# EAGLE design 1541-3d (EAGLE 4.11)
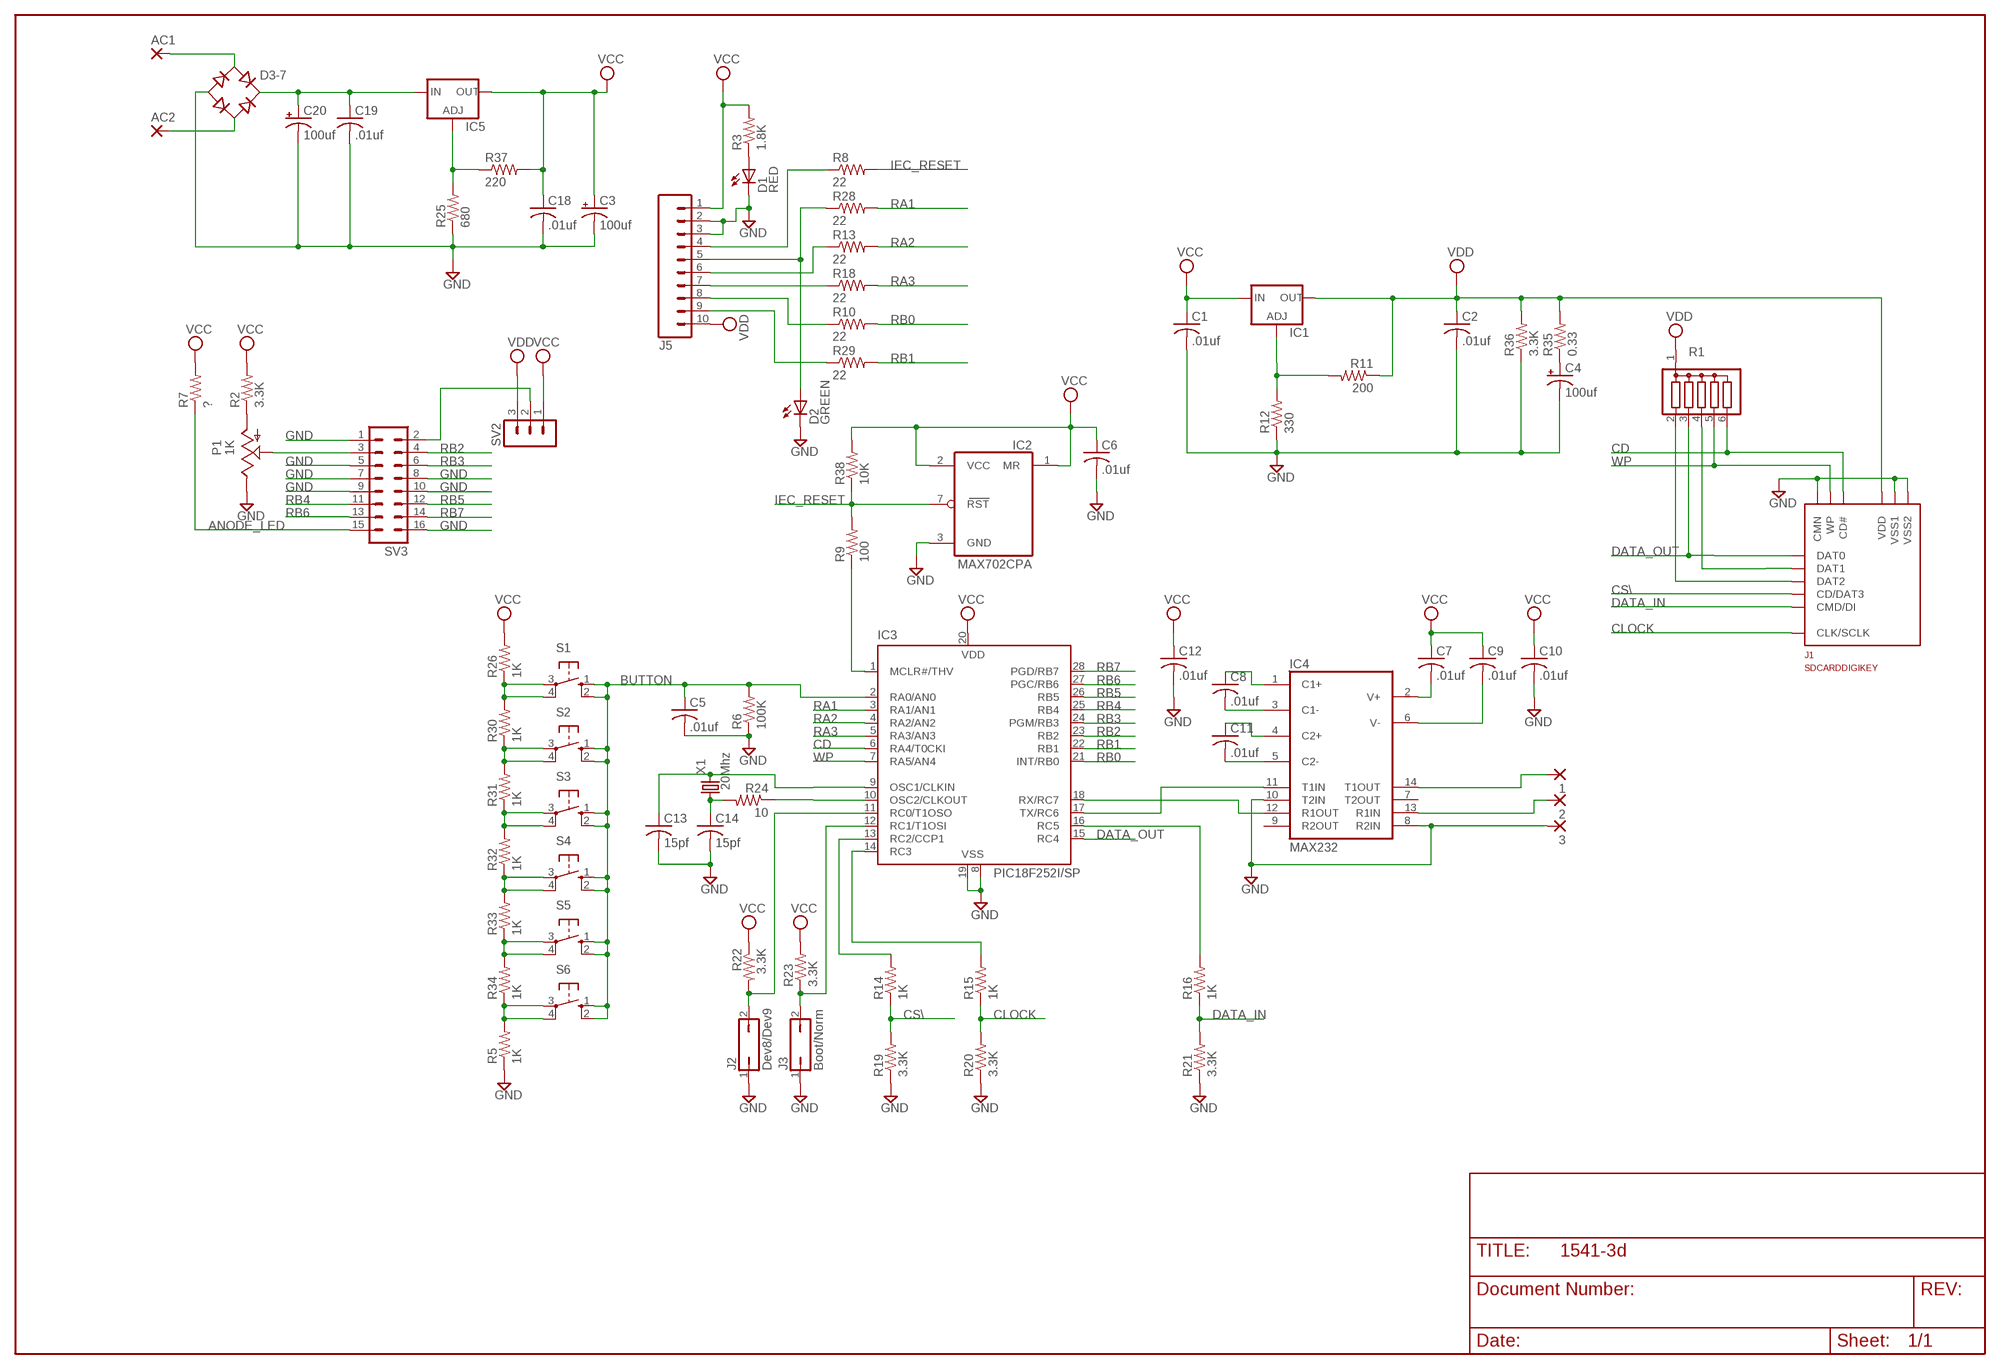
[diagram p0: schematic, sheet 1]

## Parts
1  2,15/1,0  [2,15/1,0]
2  2,15/1,0  [2,15/1,0]
3  2,15/1,0  [2,15/1,0]
AC1  2,15/1,0  [2,15/1,0]
AC2  2,15/1,0  [2,15/1,0]
C1  .01uf  C-US025-024X044  [C025-024X044]
C2  .01uf  C-US025-024X044  [C025-024X044]
C3  100uf  CPOL-USE2-5  [E2-5]
C4  100uf  CPOL-USE2-5  [E2-5]
C5  .01uf  C-US025-024X044  [C025-024X044]
C6  .01uf  C-US025-024X044  [C025-024X044]
C7  .01uf  C-US025-024X044  [C025-024X044]
C8  .01uf  C-US025-024X044  [C025-024X044]
C9  .01uf  C-US025-024X044  [C025-024X044]
C10  .01uf  C-US025-024X044  [C025-024X044]
C11  .01uf  C-US025-024X044  [C025-024X044]
C12  .01uf  C-US025-024X044  [C025-024X044]
C13  15pf  C-US025-024X044  [C025-024X044]
C14  15pf  C-US025-024X044  [C025-024X044]
C18  .01uf  C-US025-024X044  [C025-024X044]
C19  .01uf  C-US025-024X044  [C025-024X044]
C20  100uf  CPOL-USE2-5  [E2-5]
D1  RED  LED3MM  [LED3MM]
D2  GREEN  LED3MM  [LED3MM]
D3-7  RB1A  [RB1A]
IC1  LM317TS  [317TS]
IC2  MAX702CPA  [DIL08]
IC3  PIC18F252I/SP  PIC16F870P  [DIL28-3]
IC4  MAX232  [DIL16]
IC5  LM317TS  [317TS]
J1  SDCARDDIGIKEY  [WM24032]
J2  Dev8/Dev9  JP1Q  [JP1]
J3  Boot/Norm  JP1Q  [JP1]
J5  M10  [10P]
P1  1K  TRIM_US-LI10  [LI10]
R1  G05R  [SIL6]
R2  3.3K  R-US_0207/2V  [0207/2V]
R3  1.8K  R-US_0207/2V  [0207/2V]
R5  1K  R-US_0207/2V  [0207/2V]
R6  100K  R-US_0207/2V  [0207/2V]
R7  ?  R-US_0207/2V  [0207/2V]
R8  22  R-US_0207/2V  [0207/2V]
R9  100  R-US_0207/2V  [0207/2V]
R10  22  R-US_0207/2V  [0207/2V]
R11  200  R-US_0207/2V  [0207/2V]
R12  330  R-US_0207/2V  [0207/2V]
R13  22  R-US_0207/2V  [0207/2V]
R14  1K  R-US_0207/2V  [0207/2V]
R15  1K  R-US_0207/2V  [0207/2V]
R16  1K  R-US_0207/2V  [0207/2V]
R18  22  R-US_0207/2V  [0207/2V]
R19  3.3K  R-US_0207/2V  [0207/2V]
R20  3.3K  R-US_0207/2V  [0207/2V]
R21  3.3K  R-US_0207/2V  [0207/2V]
R22  3.3K  R-US_0207/2V  [0207/2V]
R23  3.3K  R-US_0207/2V  [0207/2V]
R24  10  R-US_0207/2V  [0207/2V]
R25  680  R-US_0207/2V  [0207/2V]
R26  1K  R-US_0207/2V  [0207/2V]
R28  22  R-US_0207/2V  [0207/2V]
R29  22  R-US_0207/2V  [0207/2V]
R30  1K  R-US_0207/2V  [0207/2V]
R31  1K  R-US_0207/2V  [0207/2V]
R32  1K  R-US_0207/2V  [0207/2V]
R33  1K  R-US_0207/2V  [0207/2V]
R34  1K  R-US_0207/2V  [0207/2V]
R35  0.33  R-US_0207/2V  [0207/2V]
R36  3.3K  R-US_0207/2V  [0207/2V]
R37  220  R-US_0207/2V  [0207/2V]
R38  10K  R-US_0207/2V  [0207/2V]
S1  10-XX  [B3F-10XX]
S2  10-XX  [B3F-10XX]
S3  10-XX  [B3F-10XX]
S4  10-XX  [B3F-10XX]
S5  10-XX  [B3F-10XX]
S6  10-XX  [B3F-10XX]
SV2  MA03-1  [MA03-1]
SV3  ML16  [ML16]
X1  20Mhz  CRYTALHC49U70  [HC49U70]

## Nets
ANODE_LED: R7.1 SV3.15
BUTTON: C5.1 IC3.2(RA0/AN0) R6.2 S1.1(S) S1.2(S1) S2.1(S) S2.2(S1) S3.1(S) S3.2(S1) S4.1(S) S4.2(S1) S5.1(S) S5.2(S1) S6.1(S) S6.2(S1)
CD: IC3.6(RA4/T0CKI) J1.CD(CD#) R1.6
CLOCK: J1.5(CLK/SCLK) R15.1 R20.2
CS\: J1.1(CD/DAT3) R14.1 R19.2
DATA_IN: J1.2(CMD/DI) R16.1 R21.2
DATA_OUT: IC3.15(RC4) J1.7(DAT0) R1.3
GND: 3.1(P) C1.2 C2.2 C3.- C4.- C5.2 C6.2 C10.2 C12.2 C13.2 C14.2 C18.2 C19.2 C20.- D1.K(C) D2.K(C) D3-7.- IC2.3(GND) IC3.8(VSS) IC3.19(VSS) IC4.8(R2IN) IC4.10(T2IN) J1.3(VSS1) J1.6(VSS2) J1.CMN J2.1 J3.1 J5.2 J5.3 P1.E R5.1 R6.1 R12.1 R19.1 R20.1 R21.1 R25.1 R36.1 SV3.1 SV3.5 SV3.7 SV3.8 SV3.9 SV3.10 SV3.16
IEC_RESET: IC2.7(RST) R8.2 R9.2 R38.1
N$1: C4.+ R35.1
N$2: J1.9(DAT2) R1.2
N$3: J1.8(DAT1) R1.4
N$4: J5.9 R29.1
N$5: J5.8 R10.1
N$6: J5.7 R18.1
N$7: J5.4 R8.1
N$8: D2.A J5.5 R28.1
N$9: J5.6 R13.1
N$10: D1.A R3.1
N$11: IC3.18(RX/RC7) IC4.12(R1OUT)
N$12: IC3.14(RC3) R15.2
N$13: C14.1 R24.2 X1.1
N$14: IC3.1(MCLR#/THV) R9.1
N$15: C11.1 IC4.4(C2+)
N$16: C11.2 IC4.5(C2-)
N$17: C8.2 IC4.3(C1-)
N$18: C8.1 IC4.1(C1+)
N$19: C7.2 IC4.2(V+)
N$20: C13.1 IC3.9(OSC1/CLKIN) X1.2
N$21: IC3.10(OSC2/CLKOUT) R24.1
N$22: IC3.12(RC1/T1OSI) J3.2 R23.1
N$23: IC3.11(RC0/T1OSO) J2.2 R22.2
N$24: IC3.13(RC2/CCP1) R14.2
N$25: IC3.16(RC5) R16.2
N$26: IC1.1(ADJ) R11.2 R12.2
N$27: IC3.17(TX/RC6) IC4.11(T1IN)
N$28: R26.1 R30.2 S1.3(P) S1.4(P1)
N$29: R30.1 R31.2 S2.3(P) S2.4(P1)
N$30: R31.1 R32.2 S3.3(P) S3.4(P1)
N$31: R5.2 R34.1 S6.3(P) S6.4(P1)
N$32: R33.1 R34.2 S5.3(P) S5.4(P1)
N$33: R32.1 R33.2 S4.3(P) S4.4(P1)
N$34: P1.A R2.1
N$35: SV2.2 SV3.2
N$36: P1.S SV3.3
N$37: C9.2 IC4.6(V-)
N$38: IC5.1(ADJ) R25.2 R37.1
N$39: AC1.1(P) D3-7.AC1
N$40: C19.1 C20.+ D3-7.+ IC5.3(IN)
N$41: AC2.1(P) D3-7.AC2
N$42: 2.1(P) IC4.13(R1IN)
N$43: 1.1(P) IC4.14(T1OUT)
RA1: IC3.3(RA1/AN1) R28.2
RA2: IC3.4(RA2/AN2) R13.2
RA3: IC3.5(RA3/AN3) R18.2
RB0: IC3.21(INT/RB0) R10.2
RB1: IC3.22(RB1) R29.2
RB2: IC3.23(RB2) SV3.4
RB3: IC3.24(PGM/RB3) SV3.6
RB4: IC3.25(RB4) SV3.11
RB5: IC3.26(RB5) SV3.12
RB6: IC3.27(PGC/RB6) SV3.13
RB7: IC3.28(PGD/RB7) SV3.14
VCC: C1.1 C3.+ C6.1 C7.1 C9.1 C10.1 C12.1 C18.1 IC1.3(IN) IC2.1(MR) IC2.2(VCC) IC3.20(VDD) IC5.2(OUT) J5.1 R2.2 R3.2 R7.2 R22.1 R23.2 R26.2 R37.2 R38.2 SV2.1
VDD: C2.1 IC1.2(OUT) J1.4(VDD) J5.10 R1.1 R11.1 R35.2 R36.2 SV2.3
WP: IC3.7(RA5/AN4) J1.WP R1.5
Unconnected: IC4.7(T2OUT) IC4.9(R2OUT)

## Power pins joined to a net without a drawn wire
GND: IC4.15(GND) J1.A1(GND) J1.A2(GND)
VCC: IC4.16(VCC)

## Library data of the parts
1-3 AC1 AC2 = wirepad:2,15/1,0: THROUGH-HOLE PAD
C1 C2 C5-C14 C18 C19 = rcl:C-US: CAPACITOR, American symbol
C3 C4 C20 = rcl:CPOL-US: POLARIZED CAPACITOR, American symbol
D1 D2 = led:LED: LED
D3-7 = rectifier:RB1A: RECTIFIER 1 A
IC1 IC5 = v-reg:LM317TS: VOLTAGE REGULATOR
IC2 = maxim:MAX702CPA: POWER SUPPLY MONITOR
IC3 = microchip:PIC16*870: MICROCONTROLLER flash type
IC4 = maxim:MAX232: RS232 TRANSEIVER
J1 = sdcards:SDCARD: SD Card Holder
J2 J3 = jumper:JP1Q: JUMPER
J5 = con-amp-quick:M10: AMP QUICK CONNECTOR
P1 = pot:TRIM_US-: POTENTIOMETER
R1 = resistor-sil:G05R: SIL RESISTOR
R2 R3 R5-R16 R18-R26 R28-R38 = rcl:R-US_: RESISTOR, American symbol
S1-S6 = switch-omron:10-XX: OMRON SWITCH
SV2 = con-lstb:MA03-1: PIN HEADER
SV3 = con-harting-ml:ML16: HARTING
X1 = crystal:CRYTAL: CRYSTAL

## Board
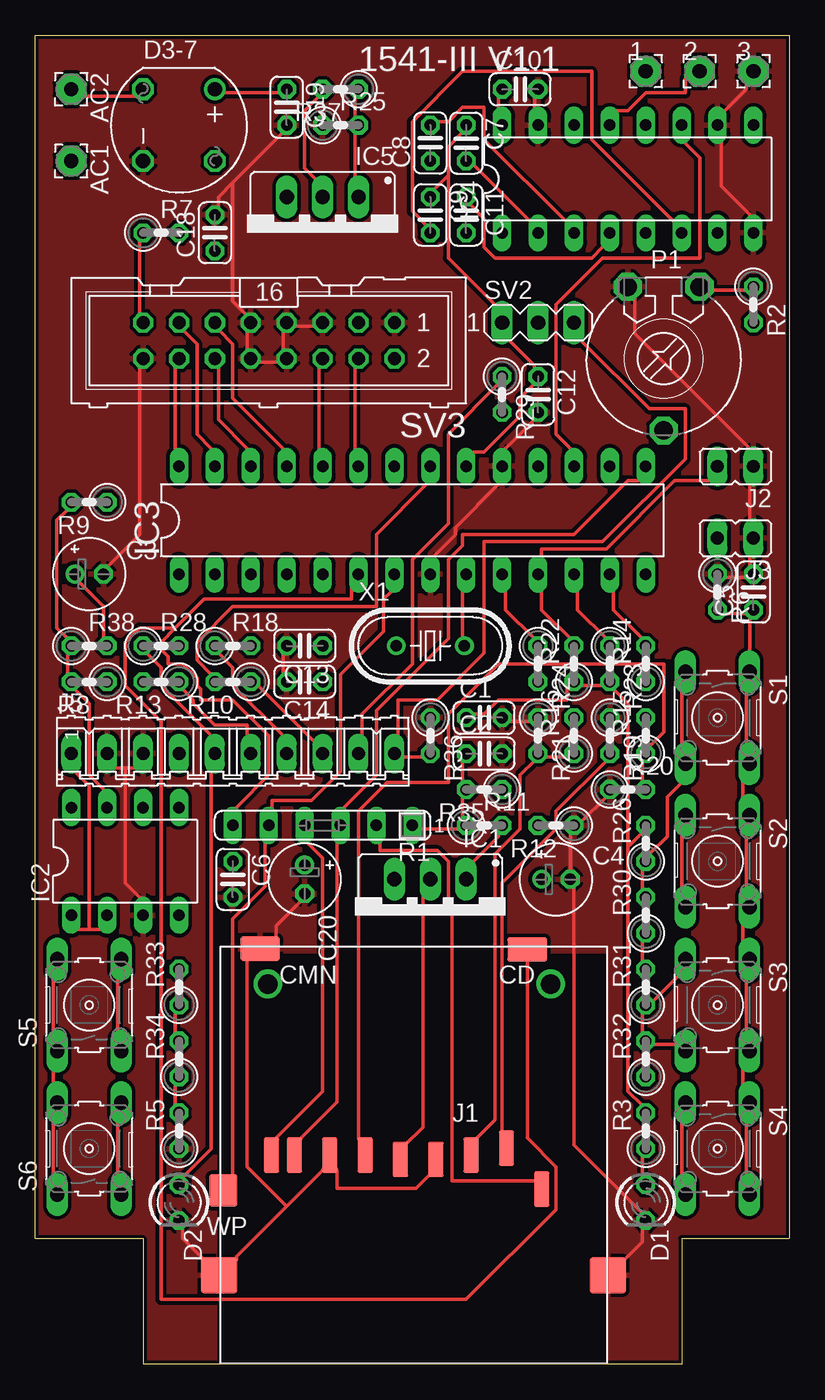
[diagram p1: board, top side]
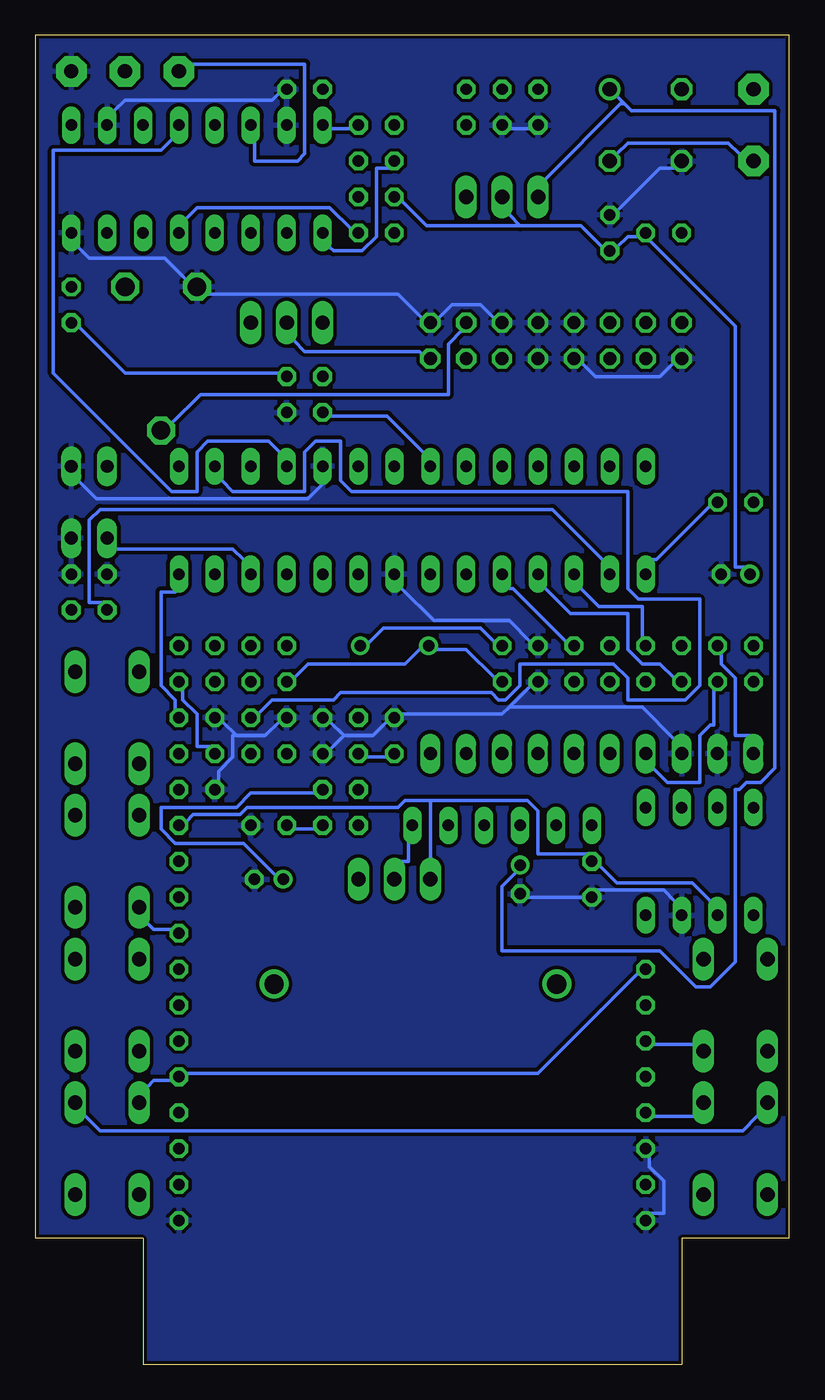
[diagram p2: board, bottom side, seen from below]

Size 53.34 x 93.98 mm. Coordinates in mm from the lower left corner, seen from the top.
Outline: 0,93.98 53.34,93.98 53.34,8.89 45.72,8.89 45.72,0 7.62,0 7.62,8.89 0,8.89 0,93.98
Copper layers (1*16): Top 0.035mm / dielectric 1.5mm / Bottom 0.035mm
Design rules "olimex10mil": minimum track width 10mil, minimum drill 24mil, track to track 10mil, track to pad 10mil, pad to pad 10mil, via to via 10mil, smd to smd 10mil, copper to edge 10mil, drill to drill 10mil, minimum pad ring 10mil, minimum via ring 8mil, stop-mask expansion 0mil, vias tented up to drill 0mil, thermal gap 10mil

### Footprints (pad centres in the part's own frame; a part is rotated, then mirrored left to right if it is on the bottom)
2,15/1,0 = drill 1.016 pad 2.159 octagon: 1 0,0
C025-024X044 = drill 0.813 octagon: 1 -1.27,0; 2 1.27,0
E2-5 = drill 0.813 pad 1.27 round: + -1.016,0 | drill 0.813 pad 1.27 octagon: - 1.016,0
LED3MM = drill 0.813 octagon: A -1.27,0; K 1.27,0
RB1A = drill 1.016 round: + -2.54,2.54 | drill 1.016 octagon: - 2.54,-2.54; AC1 2.54,2.54; AC2 -2.54,-2.54
317TS = drill 1.016 long: 1 -2.54,-2.54; 2 0,-2.54; 3 2.54,-2.54
DIL08 = drill 0.813 long: 1 -3.81,-3.81; 2 -1.27,-3.81; 3 1.27,-3.81; 4 3.81,-3.81; 5 3.81,3.81; 6 1.27,3.81; 7 -1.27,3.81; 8 -3.81,3.81
DIL28-3 = drill 0.813 long: 1 -16.51,-3.81; 2 -13.97,-3.81; 3 -11.43,-3.81; 4 -8.89,-3.81; 5 -6.35,-3.81; 6 -3.81,-3.81; 7 -1.27,-3.81; 8 1.27,-3.81; 9 3.81,-3.81; 10 6.35,-3.81; 11 8.89,-3.81; 12 11.43,-3.81; 13 13.97,-3.81; 14 16.51,-3.81; 15 16.51,3.81; 16 13.97,3.81; 17 11.43,3.81; 18 8.89,3.81; 19 6.35,3.81; 20 3.81,3.81; 21 1.27,3.81; 22 -1.27,3.81; 23 -3.81,3.81; 24 -6.35,3.81; 25 -8.89,3.81; 26 -11.43,3.81; 27 -13.97,3.81; 28 -16.51,3.81
DIL16 = drill 0.813 long: 1 -8.89,-3.81; 2 -6.35,-3.81; 3 -3.81,-3.81; 4 -1.27,-3.81; 5 1.27,-3.81; 6 3.81,-3.81; 7 6.35,-3.81; 8 8.89,-3.81; 9 8.89,3.81; 10 6.35,3.81; 11 3.81,3.81; 12 1.27,3.81; 13 -1.27,3.81; 14 -3.81,3.81; 15 -6.35,3.81; 16 -8.89,3.81
WM24032 = smd 1.1 x 2.5: 1 -6.975,-2.9; 2 -4.475,-2.4; 3 -1.975,-2.1; 4 0.525,-2.1; 5 3.025,-2.4; 6 5.525,-2.4; 7 8.025,-2.4; 8 9.65,-2.4; 9 -9.475,0 | smd 2.6 x 2.6: A1 -14.15,6.1; A2 13.35,6.1 | drill 1.36 pad 1.46 round: B1 -10.1,-14.5; B2 9.9,-14.5 | smd 2.8 x 1.7: CD -8.45,-16.95; CMN 10.45,-17 | smd 2 x 2.3: WP 13.05,0.1
JP1 = drill 0.914 long: 1 0,-1.27; 2 0,1.27
10P = drill 0.914 long: 1 -11.43,0; 2 -8.89,0; 3 -6.35,0; 4 -3.81,0; 5 -1.27,0; 6 1.27,0; 7 3.81,0; 8 6.35,0; 9 8.89,0; 10 11.43,0
LI10 = drill 1.321 octagon: A -2.54,-5.08; E 2.54,-5.08; S 0,5.08
SIL6 = drill 0.813 long: 1 -6.35,0; 2 -3.81,0; 3 -1.27,0; 4 1.27,0; 5 3.81,0; 6 6.35,0
0207/2V = drill 0.813 octagon: 1 -1.27,0; 2 1.27,0
B3F-10XX = drill 1.016 long: 1 -3.251,2.261; 2 3.251,2.261; 3 -3.251,-2.261; 4 3.251,-2.261
MA03-1 = drill 1.016 long: 1 -2.54,0; 2 0,0; 3 2.54,0
ML16 = drill 0.914 octagon: 1 -8.89,-1.27; 2 -8.89,1.27; 3 -6.35,-1.27; 4 -6.35,1.27; 5 -3.81,-1.27; 6 -3.81,1.27; 7 -1.27,-1.27; 8 -1.27,1.27; 9 1.27,-1.27; 10 1.27,1.27; 11 3.81,-1.27; 12 3.81,1.27; 13 6.35,-1.27; 14 6.35,1.27; 15 8.89,-1.27; 16 8.89,1.27
HC49U70 = drill 0.813 round: 1 -2.413,0; 2 2.413,0

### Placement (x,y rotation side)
1  43.18,91.44 0 top
2  46.99,91.44 0 top
3  50.8,91.44 0 top
AC1  2.54,85.09 270 top
AC2  2.54,90.17 270 top
C1  31.75,45.72 0 top
C2  31.75,43.18 0 top
C3  3.81,55.88 0 top
C4  36.83,34.29 0 top
C5  50.8,54.61 90 top
C6  13.97,34.29 270 top
C7  30.48,86.36 270 top
C8  27.94,86.36 90 top
C9  27.94,81.28 270 top
C10  34.29,90.17 0 top
C11  30.48,81.28 270 top
C12  35.56,68.58 270 top
C13  19.05,50.8 180 top
C14  19.05,48.26 180 top
C18  12.7,80.01 90 top
C19  17.78,88.9 270 top
C20  19.05,34.29 270 top
D1  43.18,11.43 270 top
D2  10.16,11.43 270 top
D3-7  10.16,87.63 270 top
IC1  27.94,31.75 180 top
IC2  6.35,35.56 0 top
IC3  26.67,59.69 0 top
IC4  41.91,83.82 0 top
IC5  20.32,80.01 180 top
J1  26.35,12.38 180 top
J2  49.53,63.5 90 top
J3  49.53,58.42 90 top
J5  13.97,43.18 0 top
P1  44.45,71.12 180 top
R1  20.32,38.1 180 top
R2  50.8,74.93 270 top
R3  43.18,16.51 90 top
R5  10.16,16.51 90 top
R6  48.26,54.61 270 top
R7  8.89,80.01 0 top
R8  3.81,48.26 180 top
R9  3.81,60.96 180 top
R10  13.97,48.26 180 top
R11  31.75,38.1 0 top
R12  36.83,38.1 180 top
R13  8.89,48.26 180 top
R14  43.18,49.53 90 top
R15  43.18,44.45 90 top
R16  38.1,44.45 90 top
R18  13.97,50.8 0 top
R19  40.64,44.45 270 top
R20  41.91,40.64 0 top
R21  35.56,44.45 270 top
R22  38.1,49.53 90 top
R23  40.64,49.53 270 top
R24  35.56,49.53 270 top
R25  21.59,87.63 0 top
R26  43.18,36.83 90 top
R28  8.89,50.8 0 top
R29  33.02,68.58 270 top
R30  43.18,31.75 90 top
R31  43.18,26.67 90 top
R32  43.18,21.59 90 top
R33  10.16,26.67 90 top
R34  10.16,21.59 90 top
R35  31.75,40.64 180 top
R36  27.94,44.45 270 top
R37  21.59,90.17 180 top
R38  3.81,50.8 0 top
S1  48.26,45.72 270 top
S2  48.26,35.56 270 top
S3  48.26,25.4 270 top
S4  48.26,15.24 270 top
S5  3.81,25.4 90 top
S6  3.81,15.24 90 top
SV2  35.56,73.66 0 top
SV3  16.51,72.39 180 top
X1  27.94,50.8 0 top

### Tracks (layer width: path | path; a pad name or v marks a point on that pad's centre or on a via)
ANODE_LED
  Top 0.254: R7.1 7.37,79.5 7.37,74.17 SV3.15
BUTTON
  Top 0.254: R6.2 48.77,53.09 50.29,53.09 C5.1 50.55,52.83 50.55,50.29 S1.1 50.29,47.5 50.29,43.94 S1.2 50.04,41.15 50.04,40.13 S2.1 50.29,37.34 50.29,33.78 S2.2 50.04,30.99 50.04,29.97 S3.1 50.29,27.18 50.29,23.62 S3.2 50.04,20.83 50.04,19.81 S4.1 50.29,17.02 50.29,13.46 S4.2 | S6.1 1.27,13.46 1.27,17.02 S6.2 1.27,19.81 1.27,20.83 S5.1 1.27,23.62 1.27,27.18 S5.2
  Bottom 0.254: IC3.2 13.21,56.9 16.76,60.45 48.77,60.45 49.53,59.69 49.53,53.85 48.51,53.85 R6.2 | S6.2 2.29,17.53 3.3,16.51 48.77,16.51 49.78,17.53 S4.1
CD
  Top 0.254: 9.91,52.07 11.94,54.1 22.35,54.1 22.35,54.86 IC3.6 | 9.91,52.07 8.89,51.05 8.89,50.55 9.4,50.04 9.4,49.53 10.41,49.53 11.43,48.51 11.43,48.01 11.68,47.75 11.68,46.99 13.97,46.99 16.51,44.45 16.51,41.66 14.22,39.37 R1.6 | 9.91,52.07 7.37,52.07 6.35,51.05 6.35,48.01 8.89,45.47 8.89,4.57 30.48,4.57 36.83,10.92 36.83,13.97 34.8,16 34.8,28.7 J1.CD
CLOCK
  Top 0.254: J1.5 22.86,16 22.86,39.12 24.89,41.15 29.21,41.15 29.21,45.97 32.77,49.53 44.45,49.53 44.45,44.7 43.43,43.69 R15.1 42.93,42.67 42.93,41.15 R20.2
CS\
  Top 0.254: J1.1 33.02,16.51 33.02,34.04 36.83,37.85 36.83,39.12 40.39,42.67 R19.2
  Bottom 0.254: R14.1 42.93,47.75 42.93,46.99 41.91,45.97 41.91,43.69 40.89,43.69 R19.2
DATA_IN
  Top 0.254: J1.2 31.24,16 32.51,17.27 32.51,36.07 34.29,37.85 34.29,41.66 35.31,42.67 R21.2 36.07,42.93 37.59,42.93 R16.1
DATA_OUT
  Top 0.254: J1.7 18.8,16 21.34,18.54 21.34,36.83 R1.3 21.84,39.37 24.13,41.66 24.13,46.23 29.21,51.31 29.21,56.9 30.23,57.91 30.23,58.67 38.1,58.67 41.91,62.48 42.67,62.48 IC3.15
GND
  Top 0.254: C3.- 5.08,56.39 7.37,58.67 7.37,70.61 SV3.16 | SV3.5 19.81,73.41 18.29,73.41 SV3.7 17.53,73.15 17.53,71.63 SV3.8 17.27,70.87 15.75,70.87 SV3.10 14.99,71.63 14.99,73.15 SV3.9 14.99,74.17 13.97,75.18 13.97,83.57 | 13.97,83.57 12.95,82.55 12.95,81.79 C18.2 | 13.97,83.57 17.53,87.12 C19.2 | R6.1 48.77,55.63 50.29,55.63 C5.2 50.55,56.39 50.55,57.15 J3.1 50.55,59.69 50.55,62.23 J2.1 50.55,64.77 42.42,72.9 42.42,75.44 P1.E | IC4.15 35.31,88.9 35.31,89.66 C10.2 | 3.1 50.29,90.42 50.29,90.17 48.77,88.65 IC4.10 48.51,86.36 48.51,83.31 50.55,81.28 IC4.8 | J1.3 27.94,13.46 26.92,12.45 21.34,12.45 21.34,13.72 J1.6 20.32,13.72 17.78,11.18 | D2.K 10.41,9.65 10.41,8.89 11.94,7.37 J1.A2 14.22,7.37 14.22,7.62 17.78,11.18 | C20.- 18.8,32.77 17.02,30.99 17.02,30.23 J1.CMN 14.99,28.7 14.99,13.97 17.78,11.18 | 6.35,42.16 7.11,42.16 J5.3 | 6.35,42.16 5.59,42.16 J5.2 | 6.35,42.16 6.35,34.04 7.37,33.02 IC2.3 | J1.A1 41.66,7.37 42.93,8.64 42.93,9.65 D1.K 42.93,10.67 38.1,15.49 38.1,33.78 C4.- 37.85,34.8 37.85,37.59 R12.1 38.61,38.35 40.39,40.13 R20.1 | IC3.8 28.19,57.15 29.72,58.67 29.72,59.18 32.77,62.23 IC3.19 33.27,64.77 35.31,66.8 C12.2 | C14.2 17.53,48.77 17.53,50.29 C13.2 | R21.1 35.05,45.47 33.53,45.47 C1.2
  Bottom 0.254: SV3.5 20.83,73.91 21.84,74.93 23.88,74.93 24.89,73.91 SV3.1 25.91,73.91 27.69,75.69 41.15,75.69 P1.E 42.67,76.71 44.2,78.23 49.53,78.23 50.29,78.99 IC4.8 | C19.2 18.29,87.38 19.81,87.38 R25.1 | C18.2 12.19,81.53 9.14,84.58 8.13,84.58 D3-7.- | SV3.16 8.13,70.87 9.14,69.85 13.72,69.85 14.73,70.87 SV3.10 | C10.2 36.07,89.92 36.58,89.41 46.99,89.41 47.75,88.65 IC4.10 | R5.1 9.91,14.73 9.91,13.97 8.89,12.95 8.89,10.67 9.91,10.67 D2.K | IC2.3 8.13,32.77 8.89,33.53 13.72,33.53 C6.2 14.48,33.02 18.54,33.02 C20.- | 31.5,44.45 29.46,44.45 28.45,45.47 R36.1 27.43,45.97 20.32,45.97 19.81,46.48 | 31.5,44.45 32.51,45.47 C1.2 | 31.5,44.45 32.51,43.43 C2.2 | 39.12,44.45 40.13,45.47 R19.1 | 39.12,44.45 37.08,44.45 36.07,45.47 R21.1 | 19.81,46.48 18.29,48.01 C14.2 | IC3.8 27.43,54.86 25.15,52.58 19.81,52.58 18.29,51.05 C13.2 | 39.12,44.45 39.37,44.45 39.37,42.93 40.39,41.91 40.39,41.15 R20.1 | 19.81,46.48 10.41,46.48 8.13,44.2 J5.3 | J2.1 50.29,62.48 49.02,61.21 34.04,61.21 33.02,62.23 IC3.19
  pour Bottom: 0,0 53.34,0 53.34,93.98 0,93.98
  pour Top: 0,0 12.7,0 12.7,29.21 40.64,29.21 40.64,0 53.34,0 53.34,93.98 0,93.98
IEC_RESET
  Top 0.254: R9.2 2.29,60.45 1.52,59.69 1.52,52.07 2.29,51.31 R38.1 2.29,50.29 2.29,48.77 R8.2 2.79,47.75 3.81,46.74 3.81,41.66 4.83,40.64 IC2.7
N$1
  Bottom 0.254: C4.+ 36.32,34.54 38.61,36.83 43.43,36.83 44.45,37.85 44.45,39.37 39.12,39.37 38.1,40.39 33.53,40.39 R35.1
N$2
  Top 0.254: J1.9 35.31,12.95 29.46,12.95 29.46,32.77 29.21,33.02 29.21,35.56 28.45,36.32 24.38,36.32 24.38,36.83 R1.2
N$3
  Top 0.254: J1.8 17.02,16 20.32,19.3 20.32,35.81 19.3,36.83 R1.4
N$4
  Top 0.254: R29.1 32.77,69.34 29.21,65.79 29.21,59.44 26.67,56.9 26.67,49.53 23.11,45.97 23.11,44.45 J5.9
N$5
  Top 0.254: R10.1 15.75,48.01 19.81,43.94 J5.8
N$6
  Top 0.254: R18.1 12.95,50.29 13.97,49.28 13.97,48.01 17.53,44.45 J5.7
N$7
  Bottom 0.254: R8.1 5.33,47.75 5.33,45.21 5.59,45.21 6.35,44.45 6.35,41.15 8.64,41.15 9.65,42.16 J5.4
N$8
  Top 0.254: D2.A 10.41,13.21 12.45,15.24 12.45,41.91 J5.5 12.45,44.45 8.89,48.01 8.89,49.28 7.87,50.29 R28.1
N$9
  Top 0.254: R13.1 10.41,47.75 11.18,46.99 11.18,46.74 12.7,45.21 14.99,45.21 14.99,44.45 J5.6
N$10
  Top 0.254: D1.A 42.93,13.21 42.93,14.73 R3.1
N$11
  Bottom 0.254: IC3.18 36.07,64.52 36.83,65.28 41.15,65.28 41.91,64.52 41.91,61.72 43.69,61.72 52.07,70.1 52.07,85.85 44.45,85.85 43.69,86.61 IC4.12
N$12
  Bottom 0.254: R15.2 43.43,46.23 43.43,46.99 44.45,48.01 44.45,54.61 43.43,54.61 IC3.14
N$13
  Bottom 0.254: C14.1 20.83,48.51 22.86,50.55 24.89,50.55 X1.1 26.16,50.55 27.18,49.53 34.04,49.53 35.05,48.51 R24.2
N$14
  Bottom 0.254: R9.1 5.59,60.71 9.4,56.9 9.65,56.9 IC3.1
N$15
  Top 0.254: C11.1 30.73,82.04 31.75,81.03 31.75,78.99 32.51,78.23 39.37,78.23 40.13,78.99 IC4.4
N$16
  Bottom 0.254: C11.2 30.99,80.26 32.51,81.79 41.91,81.79 42.67,81.03 IC4.5
N$17
  Top 0.254: C8.2 28.45,87.88 29.21,87.88 30.23,88.9 31.75,88.9 31.75,86.61 37.59,80.77 IC4.3
N$18
  Bottom 0.254: IC4.1 32.51,78.99 32.26,78.74 30.23,78.74 29.21,79.76 29.21,84.58 28.19,84.58 C8.1
N$19
  Top 0.254: C7.2 30.99,84.84 35.05,80.77 IC4.2
N$20
  Top 0.254: IC3.9 30.23,54.61 30.23,51.31 X1.2
  Bottom 0.254: C13.1 20.83,51.05 21.84,52.07 28.7,52.07 29.72,51.05 X1.2
N$21
  Top 0.254: R24.1 35.31,51.31 33.27,53.34 33.27,54.61 IC3.10
N$22
  Top 0.254: R23.1 40.39,51.31 38.35,53.34 38.35,54.61 IC3.12
  Bottom 0.254: J3.2 47.75,57.66 39.37,57.66 38.61,56.9 IC3.12
N$23
  Top 0.254: R22.2 37.85,51.31 35.81,53.34 35.81,54.61 IC3.11 35.81,57.15 35.81,57.66 40.39,57.66 45.21,62.48 47.75,62.48 J2.2
N$24
  Top 0.254: R14.2 42.93,51.31 40.89,53.34 40.89,54.61 IC3.13
N$25
  Bottom 0.254: R16.2 37.59,45.97 36.58,46.99 32.26,46.99 31.75,47.5 21.08,47.5 20.57,46.99 20.07,46.99 19.05,48.01 19.05,49.53 12.45,49.53 11.43,48.51 11.43,46.99 7.37,46.99 6.35,48.01 6.35,54.1 10.67,54.1 11.43,54.86 11.43,61.72 30.99,61.72 31.75,62.48 31.75,65.28 33.53,65.28 34.29,64.52 34.29,61.72 39.37,61.72 40.13,62.48 IC3.16
N$26
  Top 0.254: IC1.1 30.99,35.56 32.77,37.34 32.77,37.59 R11.2
  Bottom 0.254: R11.2 33.53,37.85 35.05,37.85 R12.2
N$27
  Top 0.254: IC3.17 37.85,64.77 36.83,65.79 36.83,74.93 40.13,78.23 46.99,78.23 46.99,85.34 45.97,86.36 IC4.11
N$28
  Top 0.254: R30.2 42.93,33.53 42.93,35.05 R26.1 43.43,36.07 44.7,37.34 44.7,40.13 45.72,41.15 S1.4 45.72,43.94 45.72,47.5 S1.3
N$29
  Top 0.254: R31.2 42.93,28.45 42.93,29.97 R30.1 | S2.3 45.72,37.34 45.72,33.78 S2.4
  Bottom 0.254: S2.4 45.47,31.24 44.96,30.73 43.69,30.73 R30.1
N$30
  Top 0.254: S3.4 45.47,22.61 43.69,22.61 R32.2 42.93,23.37 42.93,24.89 R31.1 43.69,25.65 45.47,27.43 S3.3
N$31
  Top 0.254: R5.2 9.91,18.29 9.91,19.81 R34.1 | S6.3 5.84,13.46 5.84,17.02 S6.4
  Bottom 0.254: R5.2 9.65,17.53 6.6,17.53 S6.4
N$32
  Top 0.254: R34.2 9.91,23.37 9.91,24.89 R33.1 | S5.4 5.84,27.18 5.84,23.62 S5.3
  Bottom 0.254: S5.3 6.6,22.61 9.65,22.61 R34.2
N$33
  Top 0.254: S4.4 45.72,13.46 45.72,17.02 S4.3
  Bottom 0.254: R33.2 10.67,27.69 17.78,20.57 42.67,20.57 R32.1 43.69,20.07 44.96,20.07 45.47,19.56 S4.3
N$34
  Top 0.254: R2.1 50.29,75.95 47.75,75.95 P1.A
N$35
  Bottom 0.254: SV3.2 25.91,71.37 26.16,71.63 34.29,71.63 35.05,72.39 SV2.2
N$36
  Bottom 0.254: SV3.3 23.11,73.15 24.13,72.14 24.13,68.58 41.66,68.58 43.69,66.55 P1.S
N$37
  Top 0.254: C9.2 27.69,80.52 26.67,81.53 26.67,87.88 30.23,91.44 39.37,91.44 39.37,86.61 45.21,80.77 IC4.6
N$38
  Top 0.254: R37.1 22.61,89.66 22.61,88.14 R25.2 22.61,87.12 22.61,83.82 IC5.1
N$39
  Bottom 0.254: D3-7.AC1 12.19,85.6 11.43,86.36 4.32,86.36 3.56,85.6 AC1.1
N$40
  Top 0.254: C19.1 17.27,89.92 13.21,89.92 D3-7.+
  Bottom 0.254: 11.68,89.15 12.19,89.66 D3-7.+ | 11.68,89.15 11.18,88.65 1.02,88.65 1.02,42.16 2.03,41.15 3.05,41.15 3.56,40.64 3.81,40.64 3.81,28.45 5.59,26.67 6.6,26.67 9.14,29.21 20.32,29.21 20.32,33.78 19.3,34.8 C20.+ | 11.68,89.15 11.94,89.15 17.27,83.82 IC5.3
N$41
  Top 0.254: D3-7.AC2 7.11,89.66 3.56,89.66 AC2.1
N$42
  Top 0.254: IC4.13 41.15,88.65 41.91,88.65 43.18,89.92 45.97,89.92 45.97,90.93 2.1
N$43
  Bottom 0.254: IC4.14 37.85,86.36 37.85,85.09 34.8,85.09 34.29,85.6 34.29,91.95 42.16,91.95 1.1
RA1
  Bottom 0.254: R28.2 10.41,51.31 10.41,53.59 13.46,53.59 14.73,54.86 IC3.3
RA2
  Bottom 0.254: R13.2 8.13,48.51 9.14,49.53 10.41,49.53 11.43,50.55 11.43,53.09 15.49,53.09 17.27,54.86 IC3.4
RA3
  Bottom 0.254: R18.2 15.75,51.05 19.56,54.86 19.81,54.86 IC3.5
RB0
  Top 0.254: R10.2 12.45,48.77 11.43,49.78 11.43,51.05 13.97,53.59 24.13,53.59 24.13,58.67 27.69,62.23 IC3.21
RB1
  Bottom 0.254: IC3.22 25.91,64.52 28.45,67.06 32.51,67.06 R29.2
RB2
  Top 0.254: IC3.23 22.61,64.77 22.61,70.61 SV3.4
RB3
  Top 0.254: IC3.24 20.07,64.77 20.07,70.61 SV3.6
RB4
  Top 0.254: IC3.25 17.53,64.77 13.97,68.33 13.97,72.14 12.95,73.15 SV3.11
RB5
  Top 0.254: IC3.26 14.99,64.77 12.95,66.8 12.95,70.61 SV3.12
RB6
  Top 0.254: IC3.27 12.45,64.77 11.43,65.79 11.43,72.14 10.41,73.15 SV3.13
RB7
  Top 0.254: IC3.28 9.91,64.77 9.91,70.61 SV3.14
VCC
  Top 0.254: IC3.20 30.99,64.52 31.75,64.52 34.29,67.06 34.29,68.33 35.31,69.34 C12.1 35.31,70.36 35.31,70.61 33.53,72.39 SV2.1 32.51,74.93 29.21,78.23 29.21,84.07 | IC4.16 32.77,88.9 32.77,89.66 C10.1 | 29.21,84.07 28.19,83.06 C9.1 | 29.21,84.07 29.21,86.11 30.23,87.12 C7.1 | R37.2 20.07,89.66 19.05,88.65 19.05,84.58 19.81,83.82 IC5.2 | C1.1 30.99,45.97 31.75,45.97 32.77,46.99 37.59,46.99 37.59,48.01 R22.1 38.61,48.01 40.13,48.01 R23.2 40.89,47.75 41.91,46.74 41.91,36.58 | 41.91,36.58 41.91,19.3 42.93,18.29 R3.2 | 41.91,36.58 42.93,37.59 R26.2 | C3.+ 3.05,55.37 4.83,53.59 4.83,51.31 R38.2 | 3.81,30.73 4.57,30.73 IC2.2 | 3.81,30.73 3.05,30.73 IC2.1 | 3.81,30.73 3.81,40.89 2.79,41.91 J5.1
  Bottom 0.254: R2.2 50.29,73.41 46.99,70.1 36.07,70.1 C12.1 | IC4.16 32.51,87.38 30.99,87.38 C7.1 | 19.05,80.52 14.73,80.52 13.21,78.99 C18.1 12.19,78.99 11.43,79.76 10.67,79.76 R7.2 9.91,79.5 3.81,73.41 3.81,56.39 3.05,56.39 C3.+ | 19.05,80.52 19.81,81.28 IC5.2 | 19.05,80.52 25.65,80.52 27.43,82.3 C9.1 | IC2.2 5.59,32.77 6.86,34.04 12.19,34.04 13.46,35.31 C6.1 14.22,36.07 17.78,36.07 17.78,39.12 18.54,39.88 25.4,39.88 | 25.4,39.88 25.4,35.56 IC1.3 | R38.2 4.83,50.29 4.83,49.53 3.81,48.51 3.81,44.45 2.79,44.45 J5.1 | 25.4,39.88 27.18,39.88 27.69,39.37 38.35,39.37 38.86,38.86 42.16,38.86 42.67,38.35 R26.2
VDD
  Top 0.254: J1.4 26.16,15.49 27.43,16.76 27.43,33.02 IC1.2 | C2.1 30.23,42.67 30.23,41.15 R35.2 30.23,40.13 30.23,38.61 R11.1 29.97,37.85 27.18,37.85 R1.1 | R36.2 27.43,42.93 25.91,42.93 J5.10 25.65,44.45 25.65,46.99 28.45,46.99 31.75,50.29 31.75,58.17 40.13,58.17 45.97,64.01 45.97,67.56 43.43,67.56 38.61,72.39 SV2.3
  Bottom 0.254: R1.1 26.92,36.83 26.92,35.56 27.43,35.56 IC1.2 | C2.1 29.97,42.93 28.45,42.93 R36.2
WP
  Top 0.254: J1.WP 13.97,13.21 13.97,31.5 16.26,33.78 16.26,36.83 R1.5 16.76,39.37 16.76,39.88 19.56,39.88 21.59,41.91 21.59,48.77 24.64,51.82 24.64,54.1 25.15,54.61 IC3.7

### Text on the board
tPlace: 1541-III V1.1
